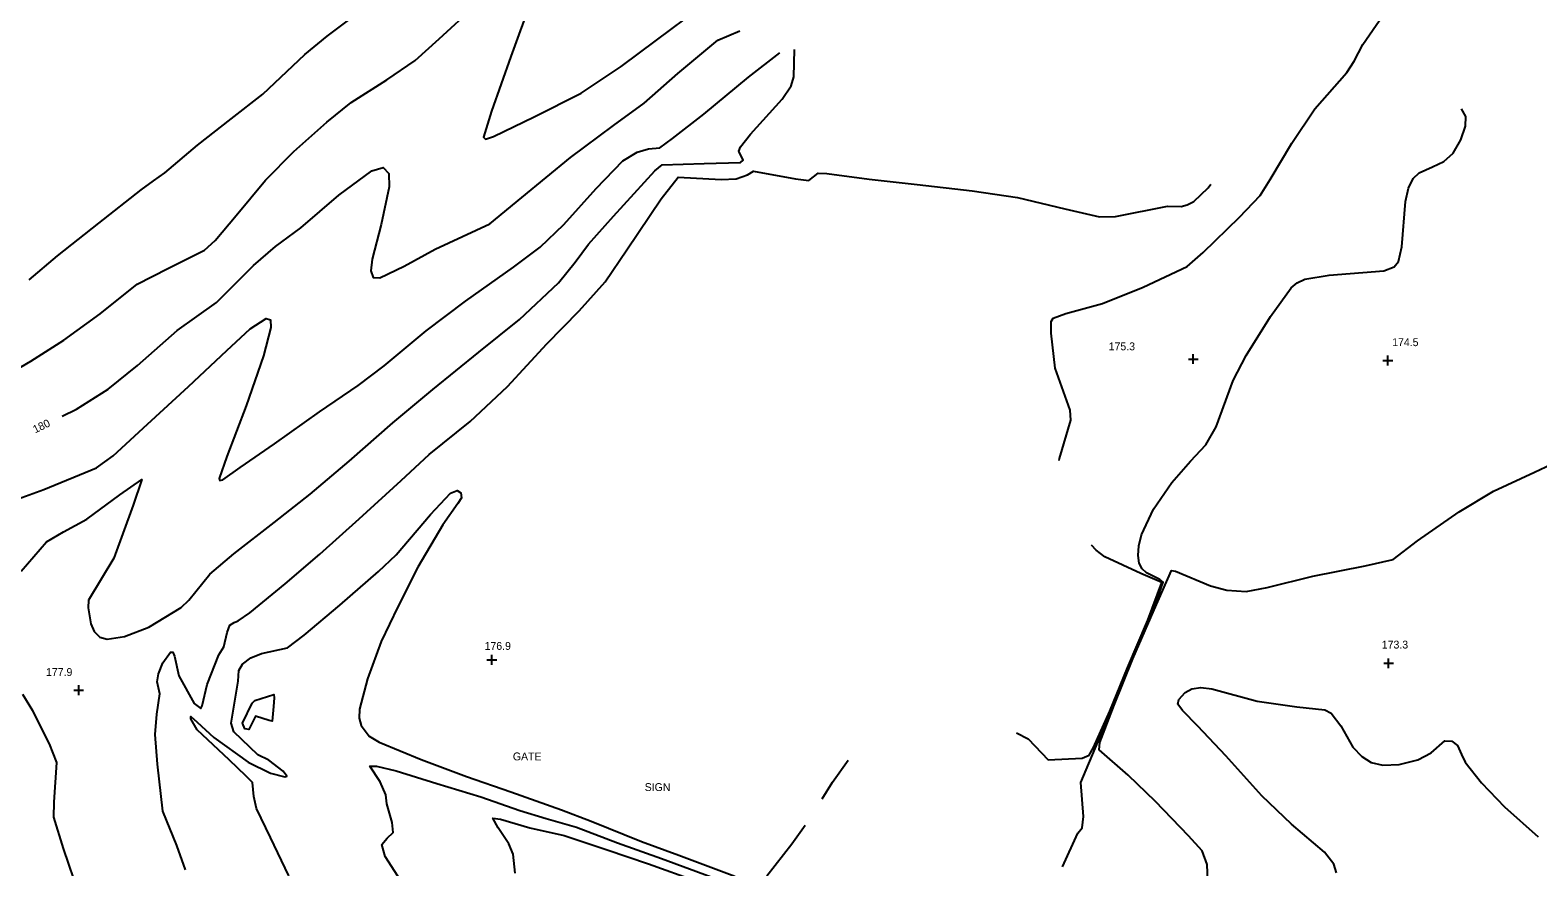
# Model space of a CAD drawing. Extents: x 1475150 to 2003689, y 770235 to 1112803.
# Drawn here: x 1995704.8 to 1996088.1, y 776771.2 to 776984.1 of the extents above; entities that cross this region are included whole.
import ezdxf

# ---------------------------------------------------------------- set-up
doc = ezdxf.new("R2010")
doc.units = 0
for name, color, linetype in [('RD_DTM_Major1', 7, 'Continuous'), ('RD_DTM_Major1_Lbl', 7, 'Continuous'), ('RD_DTM_Minor1', 7, 'Continuous'), ('RD_DTM_Spot_Elev', 7, 'Continuous'), ('RD_TX_Misc1', 7, 'Continuous')]:
    doc.layers.add(name, color=color, linetype=linetype)

msp = doc.modelspace()

# ---------------------------------------------------------------- linework, layer by layer
at = {"layer": 'RD_DTM_Major1'}
for points in [[(1995712.93, 776885.87), (1995716.51, 776887.59), (1995724.6, 776892.67), (1995732.06, 776898.7), (1995742.18, 776907.67), (1995752.14, 776914.76), (1995761.58, 776924.2), (1995767.19, 776929.01), (1995773.59, 776933.78), (1995783.29, 776942.08), (1995791.64, 776948.25), (1995794.57, 776949.12), (1995795.96, 776947.6), (1995796.04, 776944.16), (1995794.01, 776934.57), (1995791.75, 776925.8), (1995791.38, 776922.78), (1995791.96, 776921.11), (1995793.69, 776921.01), (1995799.85, 776924.04), (1995807.77, 776928.33), (1995821.64, 776934.8), (1995829.78, 776941.52), (1995842.19, 776951.63), (1995853.06, 776959.81), (1995860.91, 776965.52), (1995869.44, 776973), (1995879.64, 776981.47), (1995885.25, 776983.89)], [(1995967.25, 776771.19), (1995971.14, 776779.77), (1995972.3, 776781.13), (1995972.63, 776783.97), (1995971.92, 776792.62), (1995976.28, 776802.87), (1995980.67, 776813.6), (1995985.01, 776824.2), (1995990.21, 776836.26), (1995992.89, 776843.62), (1995992.01, 776844.29), (1995988.6, 776845.99), (1995987.56, 776847), (1995986.81, 776848.45), (1995986.5, 776850.4), (1995986.68, 776852.82), (1995987.38, 776855.64), (1995990.44, 776862.21), (1995995.05, 776868.99), (1995999.78, 776874.41), (1996003.69, 776878.53), (1996006.38, 776883.1), (1996010.66, 776894.9), (1996014.01, 776901.3), (1996020.15, 776911.22), (1996025.43, 776918.49), (1996026.95, 776919.79), (1996028.86, 776920.68), (1996035.11, 776921.7), (1996048.97, 776922.8), (1996051.65, 776923.86), (1996052.68, 776925.16), (1996053.53, 776928.95), (1996054.48, 776940.43), (1996055.25, 776943.88), (1996056.46, 776946.28), (1996058, 776947.78), (1996061.36, 776949.31), (1996064.24, 776950.6), (1996066.6, 776952.72), (1996068.57, 776956.11), (1996069.76, 776959.62), (1996069.83, 776962.05), (1996068.77, 776964.03)], [(1995765.58, 776808.42), (1995762.1, 776809.55), (1995760.34, 776806.09), (1995759.34, 776806.32), (1995758.78, 776807.72), (1995761.18, 776812.86), (1995761.86, 776813.49), (1995766.72, 776815.02), (1995766.8, 776814.16), (1995766.66, 776811.93), (1995766.3, 776808.25), (1995765.58, 776808.42)], [(1995800.58, 776765.25), (1995795, 776773.81), (1995794.18, 776776.88), (1995795.52, 776778.45), (1995797.03, 776779.89), (1995796.85, 776782.42), (1995795.43, 776787.19), (1995795.22, 776789.46), (1995793.73, 776792.81), (1995791.18, 776796.8), (1995792.84, 776796.82), (1995797.82, 776795.56), (1995808.18, 776792.37), (1995819.35, 776789.02), (1995829.3, 776785.48), (1995835.99, 776783.46), (1995843.72, 776781.3), (1995854.09, 776777.31), (1995865.31, 776773.26), (1995877.96, 776768.59)]]:
    msp.add_lwpolyline(points, dxfattribs=at)
at = {"layer": 'RD_DTM_Minor1'}
for points in [[(1995832.36, 776992.1), (1995827.03, 776977.33), (1995822.1, 776963.45), (1995820.03, 776956.84), (1995820.55, 776956.3), (1995822.6, 776957), (1995832.9, 776961.97), (1995844.88, 776968.06), (1995855.05, 776974.8), (1995864.06, 776981.5), (1995871.34, 776986.95)], [(1995700.02, 776896.93), (1995704.93, 776899.87), (1995713.3, 776905.15), (1995722.57, 776911.89), (1995731.94, 776919.4), (1995739.77, 776923.4), (1995749.13, 776928.06), (1995751.82, 776930.55), (1995757.19, 776936.92), (1995764.57, 776945.86), (1995771.85, 776953.19), (1995780.18, 776960.66), (1995786.4, 776965.61), (1995795.45, 776971.38), (1995802.69, 776976.3), (1995808.8, 776981.81), (1995817.83, 776990.2)], [(1995704.49, 776920.57), (1995711.72, 776926.6), (1995722.2, 776934.93), (1995733.03, 776943.39), (1995736.1, 776945.71), (1995739, 776947.75), (1995747.33, 776954.83), (1995755.89, 776961.53), (1995763.91, 776967.81), (1995774.62, 776977.82), (1995780.27, 776982.55), (1995791.77, 776991.09)], [(1995966.43, 776874.6), (1995966.47, 776875.11), (1995969.39, 776884.86), (1995969.24, 776887.41), (1995965.39, 776898.08), (1995964.43, 776906.92), (1995964.4, 776909.96), (1995964.94, 776910.78), (1995968.12, 776911.98), (1995977.41, 776914.5), (1995987.77, 776918.68), (1995998.98, 776923.92), (1996003.05, 776927.46), (1996012.32, 776936.49), (1996017.55, 776941.96), (1996020.06, 776946.09), (1996025.59, 776955.33), (1996031.42, 776964.07), (1996039.56, 776973.3), (1996041.41, 776976.18), (1996043.65, 776980.38), (1996048.77, 776987.75)], [(1995701.72, 776864.83), (1995708.23, 776867.16), (1995721.66, 776872.68), (1995725.85, 776875.74), (1995734.61, 776883.81), (1995745.01, 776893.38), (1995754.79, 776902.58), (1995760.71, 776908.1), (1995764.74, 776910.68), (1995765.84, 776910.33), (1995765.99, 776908.4), (1995764.13, 776901.18), (1995759.69, 776888.48), (1995754.79, 776875.59), (1995752.82, 776869.99), (1995753.02, 776869.46), (1995753.75, 776869.63), (1995758.19, 776872.76), (1995766.87, 776878.84), (1995778.3, 776886.91), (1995788.2, 776893.61), (1995794.79, 776898.64), (1995805.46, 776907.57), (1995815.48, 776915.12), (1995827.63, 776923.72), (1995834.49, 776928.87), (1995840.51, 776934.58), (1995848.69, 776943.73), (1995855.49, 776950.79), (1995859.08, 776953.01), (1995862.03, 776953.87), (1995864.9, 776954.09), (1995868.1, 776956.48), (1995876.07, 776962.66), (1995887.43, 776972.1), (1995895.39, 776978.32)], [(1995702.51, 776846.39), (1995708.94, 776853.83), (1995713.21, 776856.42), (1995719.18, 776859.62), (1995727.59, 776865.8), (1995733.17, 776869.7), (1995730.93, 776863.21), (1995726.04, 776849.69), (1995719.59, 776839.05), (1995719.49, 776837.07), (1995720.19, 776833.04), (1995721.07, 776831.04), (1995722.45, 776829.61), (1995724.35, 776829.07), (1995728.73, 776829.78), (1995734.94, 776832.17), (1995743.13, 776837.12), (1995745.08, 776839.06), (1995750.48, 776845.66), (1995756.52, 776850.83), (1995766.8, 776858.79), (1995775.95, 776865.98), (1995785.87, 776874.36), (1995796.98, 776884.13), (1995807.16, 776892.63), (1995818.86, 776902.15), (1995829.16, 776910.43), (1995839.08, 776919.79), (1995843.34, 776925.06), (1995846.75, 776929.63), (1995853.07, 776936.73), (1995863.58, 776948.27), (1995865.49, 776949.82), (1995876.14, 776950.13), (1995885.39, 776950.38), (1995886.09, 776951), (1995884.99, 776953.23), (1995885.41, 776954.41), (1995887.91, 776957.63), (1995895.99, 776966.48), (1995898.3, 776969.86), (1995898.98, 776972.2), (1995899.09, 776979.12)], [(1995744.29, 776770.42), (1995742.07, 776776.62), (1995738.5, 776785.3), (1995737.13, 776797.31), (1995736.52, 776804.86), (1995736.95, 776810.01), (1995737.73, 776815.18), (1995737.04, 776818.22), (1995737.44, 776820.24), (1995738.46, 776823.04), (1995740.41, 776825.8), (1995741.02, 776825.8), (1995741.44, 776824.76), (1995742.53, 776819.8), (1995746.46, 776812.74), (1995748.14, 776811.42), (1995748.52, 776812.18), (1995749.81, 776817.56), (1995752.72, 776825.13), (1995753.99, 776827.11), (1995754.9, 776830.84), (1995755.55, 776832.67), (1995756.61, 776833.37), (1995757.68, 776833.76), (1995760.65, 776835.82), (1995769.6, 776843.2), (1995778.39, 776850.74), (1995788.46, 776859.71), (1995799.1, 776869.49), (1995806.2, 776876.07), (1995816.61, 776884.49), (1995826.11, 776893.39), (1995836.13, 776904.28), (1995844.35, 776912.66), (1995850.99, 776920.05), (1995856.49, 776928.16), (1995865.25, 776941.1), (1995869.58, 776946.62), (1995880.49, 776946.02), (1995884.25, 776946.24), (1995887.19, 776947.23), (1995888.7, 776948.2), (1995899.37, 776946.26), (1995902.78, 776945.84), (1995905.17, 776947.65), (1995907.33, 776947.6), (1995918.07, 776946.18), (1995930.3, 776944.79), (1995944.31, 776943.16), (1995955.86, 776941.49), (1995967.85, 776938.6), (1995976.71, 776936.53), (1995980.78, 776936.66), (1995993.96, 776939.27), (1995997.43, 776939.23), (1995999, 776939.58), (1996000.65, 776940.47), (1996004.29, 776943.95), (1996004.98, 776944.9)], [(1996004.25, 776767.41), (1996004.08, 776771.75), (1996002.81, 776775.23), (1995999.3, 776779.1), (1995990.92, 776787.83), (1995983.96, 776794.47), (1995976.59, 776800.92), (1995976.78, 776802.83), (1995980.45, 776812.35), (1995985.14, 776824.08), (1995990.57, 776836.55), (1995994.99, 776846.54), (1995996.04, 776846.42), (1996004.89, 776842.66), (1996009.08, 776841.57), (1996013.98, 776841.27), (1996019.29, 776842.27), (1996030.89, 776845.14), (1996044.23, 776847.75), (1996051.36, 776849.33), (1996057.58, 776854.13), (1996068.13, 776861.52), (1996076.84, 776866.79), (1996087.32, 776871.6), (1996097.4, 776876.38)], [(1995770.56, 776768.86), (1995765.9, 776778.61), (1995762.32, 776785.99), (1995761.63, 776789.03), (1995761.33, 776792.61), (1995759.72, 776794.25), (1995755.34, 776798.41), (1995747.23, 776806.01), (1995745.59, 776808.82), (1995745.65, 776809.39), (1995747.19, 776808), (1995751.43, 776804.1), (1995760.23, 776797.79), (1995765.91, 776795.02), (1995769.51, 776794.1), (1995770.02, 776794.24), (1995769.13, 776795.54), (1995765.48, 776798.3), (1995762.7, 776799.65), (1995756.57, 776805.53), (1995755.84, 776807.73), (1995757.62, 776818.45), (1995757.85, 776821.1), (1995758.8, 776822.72), (1995760.87, 776824.31), (1995763.59, 776825.45), (1995770.21, 776826.89), (1995774.42, 776830.08), (1995783.47, 776837.74), (1995793.35, 776846.34), (1995797.84, 776850.59), (1995806.55, 776860.78), (1995811.68, 776866.22), (1995813.32, 776866.95), (1995814.26, 776866.3), (1995814.41, 776865.06), (1995813.53, 776863.63), (1995809.66, 776858.18), (1995803.31, 776847.43), (1995798.28, 776837.35), (1995793.98, 776828.48), (1995790.52, 776819.05), (1995788.48, 776811.26), (1995788.44, 776808.99), (1995788.91, 776807.12), (1995790.97, 776804.43), (1995793.5, 776802.92), (1995804.23, 776798.45), (1995815.74, 776794.18), (1995826.97, 776790.28), (1995839.9, 776785.71), (1995847.38, 776782.8), (1995860.23, 776777.66), (1995869.75, 776774.12), (1995883.91, 776768.84)], [(1995955.57, 776805.27), (1995958.52, 776803.71), (1995963.62, 776798.42), (1995972.28, 776798.79), (1995974.06, 776799.62), (1995975.17, 776801.52), (1995979.3, 776810.78), (1995983.83, 776821.83), (1995988.97, 776833.95), (1995992.56, 776843.48), (1995987.23, 776845.84), (1995978.04, 776850.04), (1995975.81, 776851.77), (1995974.66, 776853.02)], [(1996036.96, 776769.66), (1996036.25, 776771.82), (1996033.88, 776774.93), (1996025.5, 776782.06), (1996017.95, 776789.2), (1996008.77, 776799.38), (1996001.71, 776806.93), (1995997.82, 776810.96), (1995996.57, 776812.59), (1995996.87, 776813.73), (1995998.47, 776815.55), (1996000.19, 776816.47), (1996002.44, 776816.82), (1996005.24, 776816.46), (1996016.74, 776813.36), (1996026.85, 776811.87), (1996033.95, 776811.08), (1996035.56, 776810.25), (1996038.03, 776807.05), (1996041.1, 776801.63), (1996043.35, 776799.26), (1996045.8, 776797.75), (1996048.76, 776797.04), (1996052.89, 776797.25), (1996057.59, 776798.37), (1996061.02, 776800.17), (1996064.53, 776803.21), (1996066.29, 776803.16), (1996067.7, 776802.07), (1996068.77, 776799.75), (1996069.63, 776797.81), (1996073.84, 776792.57), (1996079.63, 776786.45), (1996088.23, 776778.77)], [(1995700.03, 776715.69), (1995711.1, 776717.03), (1995712.34, 776717.96), (1995712.77, 776720.84), (1995713.6, 776723.66), (1995716.48, 776728.7), (1995720.38, 776734.14), (1995723.28, 776735.7), (1995727.5, 776737.64), (1995727.37, 776738.39), (1995725.22, 776741.48), (1995716.19, 776751.95), (1995715.11, 776753.3), (1995717.31, 776757.79), (1995717.84, 776760.69), (1995717.25, 776764.15), (1995713.27, 776775.83), (1995710.75, 776783.8), (1995710.83, 776787.66), (1995711.52, 776797.73), (1995709.69, 776802.45), (1995705.44, 776810.83), (1995702.87, 776815.06)], [(1995906.16, 776788.49), (1995908.82, 776792.74), (1995912.75, 776798.32)], [(1995828.08, 776769.57), (1995827.61, 776774.36), (1995826.51, 776777.06), (1995823.78, 776781.14), (1995822.42, 776783.55), (1995824.33, 776783.29), (1995831.85, 776781.13), (1995840.52, 776779.17), (1995851.52, 776775.51), (1995862, 776771.9), (1995874.3, 776767.49)], [(1995892.13, 776768.89), (1995898.44, 776777.06), (1995901.85, 776781.74)]]:
    msp.add_lwpolyline(points, dxfattribs=at)
at = {"layer": 'RD_DTM_Spot_Elev'}
for p, q in [((1995999.29, 776900.37), (1996001.79, 776900.37)), ((1996000.54, 776899.12), (1996000.54, 776901.62)), ((1996048.75, 776900), (1996051.25, 776900)), ((1996050, 776898.75), (1996050, 776901.25)), ((1995820.92, 776823.85), (1995823.42, 776823.85)), ((1995822.17, 776822.6), (1995822.17, 776825.1)), ((1996050.2, 776821.71), (1996050.2, 776824.21)), ((1996048.95, 776822.96), (1996051.45, 776822.96)), ((1995715.87, 776816.12), (1995718.37, 776816.12)), ((1995717.12, 776814.87), (1995717.12, 776817.37))]:
    msp.add_line(p, q, dxfattribs=at)

# ---------------------------------------------------------------- texts
at = {"layer": 'RD_DTM_Major1_Lbl'}
msp.add_text('180', height=2, rotation=25.6576, dxfattribs=at).set_placement((1995706.04, 776881.45))
at = {"layer": 'RD_DTM_Spot_Elev'}
for s, p in [('175.3', (1995979.02, 776902.6)), ('174.5', (1996051.11, 776903.66)), ('176.9', (1995820.32, 776826.38)), ('173.3', (1996048.47, 776826.72)), ('177.9', (1995708.8, 776819.74))]:
    msp.add_text(s, height=2, dxfattribs=at).set_placement(p)
at = {"layer": 'RD_TX_Misc1'}
for s, p in [('GATE', (1995827.51, 776798.26)), ('SIGN', (1995861.03, 776790.46))]:
    msp.add_text(s, height=2, dxfattribs=at).set_placement(p)

doc.saveas('drawing.dxf')
